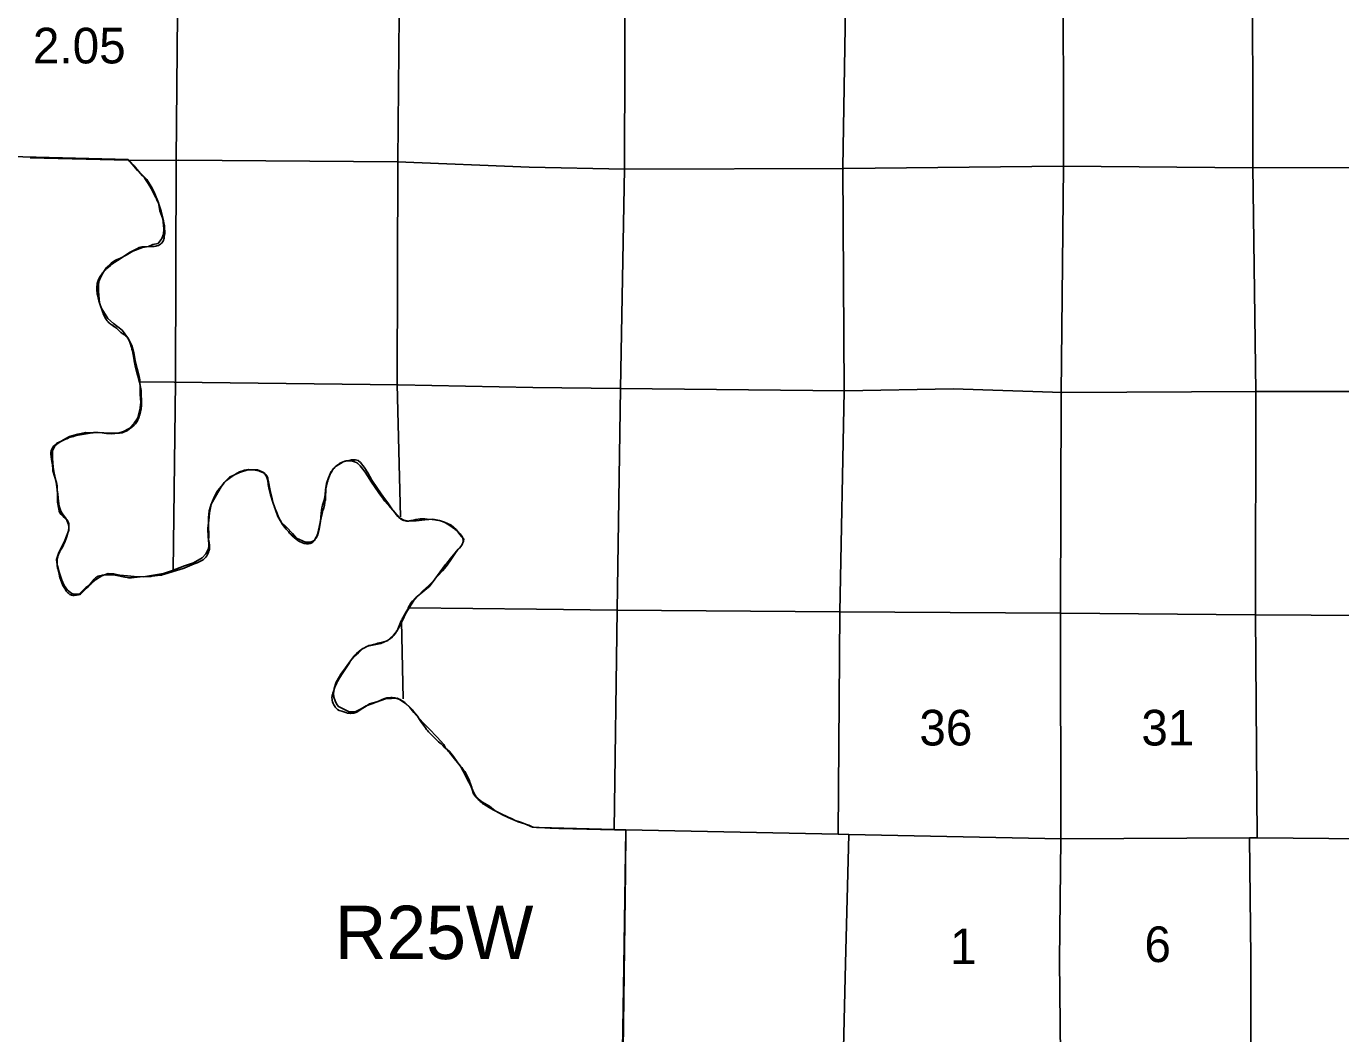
# Model space of a CAD drawing. Extents: x 77230 to 630905, y 790554 to 1662844.
# Drawn here: x 393234 to 424390, y 1547927 to 1571817 of the extents above; entities that cross this region are included whole.
import ezdxf

# ---------------------------------------------------------------- set-up
doc = ezdxf.new("R2010")
doc.units = 0
for name, color, linetype in [('Level 15', 7, 'Continuous'), ('Level 16', 7, 'Continuous'), ('Level 18', 7, 'Continuous'), ('Level 28', 7, 'Continuous'), ('Level 32', 7, 'Continuous'), ('Level 43', 7, 'Continuous')]:
    doc.layers.add(name, color=color, linetype=linetype)

msp = doc.modelspace()

# ---------------------------------------------------------------- linework, layer by layer
at = {"layer": 'Level 15'}
for points in [[(417840, 1586717), (417864, 1584365), (417830, 1579015), (417810, 1573772), (417815, 1568484), (417765, 1563114), (417749, 1557907), (417758, 1552537), (417724, 1549661)], [(434907, 1552506), (432953, 1552522), (432823, 1552523), (427671, 1552544), (427513, 1552528), (422410, 1552574), (422224, 1552572), (417760, 1552549), (412728, 1552648), (412474, 1552660), (407442, 1552760)], [(417724, 1549661), (417746, 1547411), (417738, 1542145), (417700, 1536906), (417692, 1531584), (417689, 1526263)]]:
    msp.add_lwpolyline(points, dxfattribs=at)
at = {"layer": 'Level 16'}
for points in [[(407446, 1584446), (407536, 1579006), (407433, 1573713), (407417, 1568435), (407322, 1563225), (407238, 1557970), (407168, 1552768)], [(412712, 1584452), (412696, 1578980), (412675, 1573704), (412585, 1568465), (412617, 1563165), (412520, 1557929), (412474, 1552660)], [(422260, 1579068), (422260, 1579059), (422302, 1573763), (422310, 1568489), (422377, 1563158), (422369, 1557864), (422410, 1552574)], [(402143, 1575558), (402087, 1573847), (402040, 1568615), (402028, 1563319), (402103, 1560186)], [(396845, 1574644), (396835, 1573856), (396784, 1568648), (396769, 1563376), (396713, 1558915)], [(405151, 1568475), (402032, 1568602), (396832, 1568645), (395671, 1568636)], [(430925, 1568456), (427612, 1568479), (422304, 1568459), (417811, 1568498), (412609, 1568441), (407419, 1568429), (405151, 1568475)], [(405240, 1563250), (402052, 1563317), (396741, 1563379), (395933, 1563387)], [(431276, 1563155), (427652, 1563159), (422379, 1563158), (417795, 1563132), (415205, 1563219), (412635, 1563175), (407312, 1563229), (405240, 1563250)], [(405330, 1557994), (402311, 1558024)], [(435168, 1557795), (432929, 1557807), (427665, 1557826), (422359, 1557864), (417755, 1557897), (412512, 1557933), (407238, 1557972), (405330, 1557994)], [(402128, 1557709), (402166, 1555869)], [(412728, 1552648), (412648, 1549591)], [(422224, 1552572), (422260, 1549746)], [(422260, 1549746), (422258, 1547455), (422316, 1542130), (422366, 1536889), (422412, 1531588), (422437, 1526179), (422367, 1520911)], [(412648, 1549591), (412604, 1547573), (412546, 1542289), (412502, 1537017), (412488, 1531718), (412435, 1526374)]]:
    msp.add_lwpolyline(points, dxfattribs=at)
at = {"layer": 'Level 18'}
for points in [[(393861, 1561471), (393855, 1561559), (393855, 1561691), (393858, 1561747), (393871, 1561791), (393916, 1561872), (393987, 1561928), (394115, 1562010), (394258, 1562089), (394455, 1562142), (394642, 1562184), (394821, 1562179), (394974, 1562186), (395139, 1562161), (395263, 1562153), (395415, 1562168), (395540, 1562208), (395669, 1562276), (395793, 1562409), (395874, 1562531), (395925, 1562710), (395950, 1562894), (395934, 1563094), (395932, 1563227), (395928, 1563435), (395911, 1563511), (395861, 1563690), (395814, 1563895), (395786, 1564075), (395735, 1564246), (395654, 1564407), (395503, 1564607), (395403, 1564689), (395300, 1564769), (395169, 1564885), (395104, 1564988), (395007, 1565141), (394969, 1565260), (394948, 1565528), (394947, 1565670), (394955, 1565761), (395003, 1565872), (395050, 1565965), (395128, 1566092), (395244, 1566198), (395348, 1566272), (395452, 1566314), (395604, 1566389), (395763, 1566484), (395985, 1566572), (396131, 1566597), (396236, 1566645), (396356, 1566665), (396449, 1566785), (396484, 1566888), (396493, 1567014), (396473, 1567248), (396403, 1567437), (396364, 1567631), (396282, 1567841), (396213, 1567992), (396090, 1568182), (396014, 1568265), (395870, 1568399), (395823, 1568452), (395751, 1568539), (395671, 1568636), (395649, 1568655), (391586, 1568764)], [(401097, 1561517), (401034, 1561536), (400942, 1561539), (400747, 1561485), (400581, 1561384), (400457, 1561257), (400398, 1561110), (400350, 1560975), (400327, 1560831), (400317, 1560706), (400292, 1560576), (400254, 1560461), (400239, 1560394), (400227, 1560274), (400207, 1560075), (400200, 1560025), (400178, 1559884), (400146, 1559760), (400108, 1559679), (400041, 1559614), (399967, 1559582), (399851, 1559582), (399640, 1559678), (399546, 1559789), (399399, 1559936), (399275, 1560056), (399194, 1560193), (399131, 1560376), (399074, 1560531), (399019, 1560705), (398982, 1560868), (398968, 1560948), (398956, 1561048), (398927, 1561144), (398873, 1561227), (398825, 1561254), (398716, 1561298), (398508, 1561306), (398291, 1561238), (398053, 1561122), (397921, 1561001), (397851, 1560892), (397746, 1560706), (397620, 1560485), (397571, 1560328), (397552, 1560167), (397551, 1559981), (397560, 1559733), (397556, 1559617), (397557, 1559563), (397563, 1559479), (397542, 1559410), (397486, 1559307), (397399, 1559209), (397197, 1559096), (396981, 1559022), (396677, 1558900), (396488, 1558842), (396298, 1558805), (396013, 1558760), (395787, 1558768), (395635, 1558783), (395450, 1558798), (395303, 1558835), (395171, 1558839), (395026, 1558784), (394878, 1558687), (394764, 1558587), (394647, 1558505), (394576, 1558439), (394486, 1558354), (394380, 1558354), (394310, 1558364), (394210, 1558449), (394134, 1558559), (394080, 1558683), (394010, 1558872), (393974, 1559021), (393958, 1559105), (393953, 1559171), (394002, 1559338), (394089, 1559514), (394147, 1559619), (394244, 1559869), (394244, 1559907), (394243, 1559957), (394228, 1560021), (394198, 1560105), (394190, 1560121), (394161, 1560164), (394091, 1560253), (394052, 1560322), (394012, 1560440), (393992, 1560626), (393979, 1560732), (393963, 1560822), (393948, 1560960), (393926, 1561077), (393894, 1561217), (393873, 1561353), (393861, 1561471)], [(405384, 1552821), (405236, 1552828), (405051, 1552907), (404950, 1552945), (404821, 1552982), (404654, 1553058), (404524, 1553121), (404351, 1553214), (404211, 1553322), (404100, 1553386), (404029, 1553429), (403943, 1553495), (403893, 1553547), (403837, 1553618), (403793, 1553739), (403755, 1553836), (403691, 1553947), (403656, 1554025), (403589, 1554150), (403534, 1554253), (403445, 1554378), (403361, 1554498), (403265, 1554617), (403171, 1554701), (403132, 1554789), (402973, 1554958), (402775, 1555161), (402650, 1555295), (402552, 1555395), (402418, 1555541), (402322, 1555661), (402220, 1555755), (402092, 1555843), (402025, 1555882), (401889, 1555878), (401748, 1555867), (401525, 1555793), (401428, 1555747), (401292, 1555701), (401170, 1555632), (401027, 1555556), (400887, 1555561), (400633, 1555683), (400604, 1555722), (400571, 1555784), (400554, 1555817), (400526, 1555907), (400513, 1555991), (400531, 1556113), (400582, 1556267), (400689, 1556457), (400800, 1556601), (400921, 1556773), (400999, 1556865), (401106, 1556961), (401206, 1557053), (401321, 1557117), (401476, 1557148), (401638, 1557179), (401798, 1557254), (401934, 1557381), (402015, 1557472), (402086, 1557600), (402160, 1557745), (402223, 1557887), (402306, 1558030), (402423, 1558203), (402527, 1558321), (402635, 1558429), (402775, 1558553), (402871, 1558653), (402987, 1558784), (403103, 1558902), (403183, 1559005), (403285, 1559140), (403388, 1559304), (403450, 1559387), (403499, 1559444), (403554, 1559515), (403600, 1559604), (403605, 1559658), (403513, 1559769), (403429, 1559879), (403303, 1559987), (403146, 1560058), (403027, 1560098), (402871, 1560127), (402677, 1560112), (402475, 1560086), (402299, 1560081), (402185, 1560103), (402084, 1560161), (401916, 1560347), (401807, 1560519), (401703, 1560649), (401555, 1560855), (401427, 1561053), (401328, 1561229), (401246, 1561358), (401158, 1561472), (401097, 1561517)], [(405384, 1552821), (407168, 1552768), (407442, 1552760), (407401, 1549518)], [(407401, 1549518), (407365, 1547542), (407301, 1542250), (407239, 1536976), (407211, 1531759), (409819, 1531746), (409752, 1526450), (412435, 1526374), (417689, 1526263), (417667, 1520973), (417653, 1515469), (417654, 1515315), (422612, 1515279), (427579, 1515225)]]:
    msp.add_lwpolyline(points, dxfattribs=at)
at = {"layer": 'Level 43'}
for points in [[(393328, 1568699), (395647, 1568640), (395656, 1568633), (395671, 1568622), (395694, 1568602), (395723, 1568572), (395746, 1568548), (395788, 1568505), (395820, 1568466), (395894, 1568383), (395989, 1568274)], [(395989, 1568274), (396033, 1568223), (396047, 1568205), (396061, 1568184), (396104, 1568114), (396162, 1568022), (396179, 1567995), (396190, 1567973), (396305, 1567759), (396318, 1567726), (396339, 1567681), (396356, 1567643), (396389, 1567552), (396407, 1567501), (396427, 1567434), (396483, 1567214), (396495, 1567143), (396508, 1567082), (396511, 1567044), (396516, 1566926), (396515, 1566904)], [(396515, 1566904), (396503, 1566831), (396499, 1566796), (396493, 1566767), (396484, 1566740), (396471, 1566715), (396458, 1566691), (396444, 1566676), (396430, 1566662), (396415, 1566652), (396392, 1566637), (396364, 1566622), (396332, 1566607), (396303, 1566601), (396265, 1566594), (396242, 1566593), (396226, 1566592), (395993, 1566587), (395969, 1566584), (395941, 1566576), (395912, 1566567), (395868, 1566549), (395684, 1566450), (395457, 1566303), (395334, 1566220), (395310, 1566204), (395279, 1566183), (395257, 1566166)], [(395257, 1566166), (395229, 1566145), (395142, 1566071), (395117, 1566049), (395090, 1566022), (395065, 1565993), (395044, 1565968), (395021, 1565938), (395000, 1565908), (394988, 1565892), (394975, 1565871), (394961, 1565844), (394947, 1565813), (394937, 1565789), (394927, 1565763), (394921, 1565742), (394917, 1565727), (394912, 1565688), (394908, 1565647), (394906, 1565607), (394907, 1565569), (394909, 1565535), (394911, 1565503), (394914, 1565483), (394916, 1565471), (394920, 1565450), (394955, 1565307), (395046, 1565028), (395059, 1564995), (395072, 1564965), (395092, 1564921), (395116, 1564882), (395128, 1564865), (395154, 1564830), (395171, 1564809), (395191, 1564788), (395208, 1564773), (395222, 1564762), (395245, 1564744), (395261, 1564735), (395312, 1564701), (395339, 1564684), (395351, 1564675), (395374, 1564656)], [(395374, 1564656), (395398, 1564634), (395429, 1564605), (395453, 1564581), (395475, 1564559), (395487, 1564550), (395508, 1564535), (395561, 1564502), (395576, 1564491), (395578, 1564489), (395591, 1564477), (395605, 1564463), (395620, 1564448), (395627, 1564439), (395637, 1564426), (395667, 1564373), (395678, 1564346), (395703, 1564276), (395715, 1564243), (395727, 1564206), (395738, 1564163), (395748, 1564123), (395759, 1564077), (395767, 1564036), (395785, 1563943), (395794, 1563887), (395802, 1563846), (395826, 1563724), (395866, 1563571), (395870, 1563555), (395879, 1563526), (395914, 1563380), (395948, 1563222), (395951, 1563203), (395954, 1563180), (395957, 1563159), (395957, 1563137), (395968, 1562888), (395967, 1562859), (395964, 1562827), (395956, 1562747), (395942, 1562671), (395921, 1562588), (395912, 1562557), (395904, 1562538), (395895, 1562519), (395879, 1562486), (395867, 1562463), (395853, 1562438), (395837, 1562414), (395820, 1562390), (395789, 1562360), (395734, 1562309), (395707, 1562286), (395680, 1562267), (395635, 1562234), (395600, 1562215), (395565, 1562199)], [(395565, 1562199), (395537, 1562188), (395504, 1562179), (395477, 1562173), (395442, 1562169), (395382, 1562168), (395213, 1562168), (394939, 1562182), (394907, 1562184), (394874, 1562184), (394838, 1562181), (394814, 1562179), (394794, 1562175), (394465, 1562117), (394422, 1562109), (394396, 1562102), (394355, 1562091), (394254, 1562063), (394224, 1562051), (394191, 1562037), (394161, 1562024), (394129, 1562009), (394001, 1561950), (393974, 1561936), (393953, 1561923), (393930, 1561903), (393907, 1561883), (393888, 1561865), (393873, 1561846), (393857, 1561824), (393847, 1561808), (393836, 1561787), (393829, 1561769), (393823, 1561750), (393816, 1561721), (393815, 1561699), (393817, 1561669), (393823, 1561603), (393832, 1561541), (393842, 1561495), (393849, 1561459), (393852, 1561435), (393854, 1561414), (393860, 1561314), (393863, 1561290), (393866, 1561272), (393901, 1561152), (393946, 1561019), (393950, 1561004), (393952, 1560995), (393958, 1560959), (393964, 1560927), (393969, 1560847), (393973, 1560709), (393974, 1560634), (393973, 1560585), (393973, 1560562), (393974, 1560545), (393976, 1560530), (393979, 1560495), (393987, 1560447), (394012, 1560325), (394015, 1560312), (394022, 1560291), (394030, 1560277), (394060, 1560241), (394108, 1560190), (394166, 1560147), (394181, 1560135), (394193, 1560123), (394204, 1560110), (394213, 1560097), (394221, 1560083), (394230, 1560065), (394235, 1560044), (394241, 1560022), (394243, 1560002), (394244, 1559980), (394244, 1559954), (394241, 1559895), (394238, 1559880)], [(397690, 1560654), (397702, 1560679), (397716, 1560705), (397729, 1560731), (397739, 1560750), (397754, 1560774), (397777, 1560807), (397850, 1560900), (397873, 1560931), (397892, 1560954), (397924, 1560989), (397955, 1561019), (397982, 1561042), (398067, 1561111), (398085, 1561124), (398102, 1561136), (398129, 1561154), (398172, 1561180), (398219, 1561212), (398248, 1561229), (398271, 1561242), (398288, 1561250), (398312, 1561259), (398341, 1561269), (398368, 1561278), (398386, 1561284), (398405, 1561288), (398437, 1561293), (398459, 1561296), (398497, 1561299), (398524, 1561299)], [(398524, 1561299), (398572, 1561298), (398662, 1561292), (398687, 1561288), (398703, 1561285), (398724, 1561280), (398742, 1561275), (398760, 1561268), (398780, 1561260), (398814, 1561245), (398854, 1561224), (398874, 1561213), (398894, 1561199), (398906, 1561191), (398917, 1561180), (398928, 1561168), (398938, 1561154), (398946, 1561141), (398952, 1561125), (398956, 1561110), (398963, 1561089), (398970, 1561056), (399018, 1560808), (399062, 1560607), (399079, 1560532), (399094, 1560485), (399109, 1560442), (399128, 1560391), (399155, 1560325), (399203, 1560202), (399249, 1560108), (399308, 1560005), (399328, 1559974), (399394, 1559895), (399446, 1559834), (399475, 1559800), (399502, 1559772), (399539, 1559737), (399584, 1559697), (399671, 1559624), (399694, 1559607), (399711, 1559597), (399819, 1559555), (399841, 1559551), (399860, 1559548), (399884, 1559546), (399900, 1559545), (399919, 1559547), (399940, 1559549), (399962, 1559555), (399988, 1559563), (400005, 1559571), (400027, 1559586)], [(400027, 1559586), (400041, 1559598), (400053, 1559610), (400064, 1559626), (400075, 1559645), (400106, 1559703), (400119, 1559727), (400137, 1559776), (400148, 1559806), (400163, 1559868), (400200, 1560053), (400211, 1560105), (400223, 1560159), (400244, 1560256), (400254, 1560300), (400263, 1560336), (400276, 1560375), (400299, 1560462), (400314, 1560532), (400318, 1560560), (400323, 1560586), (400325, 1560603), (400327, 1560639), (400328, 1560671), (400331, 1560807), (400332, 1560824), (400335, 1560848), (400350, 1560920), (400372, 1561015), (400378, 1561038), (400388, 1561069), (400405, 1561116), (400421, 1561156), (400437, 1561193), (400444, 1561208), (400460, 1561239), (400473, 1561262), (400485, 1561283), (400511, 1561319), (400529, 1561341), (400548, 1561361), (400573, 1561384), (400586, 1561396), (400616, 1561419), (400642, 1561436), (400669, 1561453), (400704, 1561472), (400743, 1561488), (400783, 1561503), (400800, 1561508), (400814, 1561510), (400837, 1561513), (400863, 1561515), (400901, 1561515), (400933, 1561513), (400954, 1561509), (400966, 1561506), (400993, 1561498), (401008, 1561493), (401033, 1561484), (401058, 1561471), (401071, 1561461), (401091, 1561446), (401108, 1561432), (401133, 1561409), (401147, 1561395), (401179, 1561357), (401267, 1561242), (401420, 1561005), (401578, 1560779), (401608, 1560731), (401653, 1560669)], [(397545, 1559325), (397551, 1559340), (397561, 1559369), (397575, 1559414), (397578, 1559437), (397579, 1559460), (397578, 1559491), (397576, 1559515), (397567, 1559576), (397552, 1559658), (397547, 1559688), (397544, 1559719), (397542, 1559746), (397540, 1559859), (397540, 1559885), (397541, 1559916), (397558, 1560096), (397576, 1560279), (397579, 1560297), (397584, 1560322), (397618, 1560478), (397623, 1560499), (397628, 1560515), (397690, 1560654)], [(401653, 1560669), (401685, 1560623), (401704, 1560593), (401732, 1560558), (401792, 1560488), (401827, 1560450), (401925, 1560339), (401944, 1560316), (402005, 1560239), (402044, 1560191), (402066, 1560170), (402086, 1560152), (402100, 1560140), (402118, 1560126), (402140, 1560115), (402163, 1560105), (402184, 1560099), (402204, 1560094), (402213, 1560091), (402231, 1560087), (402253, 1560084), (402269, 1560083), (402295, 1560085), (402317, 1560087), (402338, 1560090), (402360, 1560095), (402444, 1560114), (402464, 1560118), (402526, 1560130), (402568, 1560136), (402588, 1560138), (402604, 1560137), (402633, 1560137), (402681, 1560133), (402734, 1560130), (402851, 1560122), (402885, 1560119), (402914, 1560114), (402941, 1560111), (402966, 1560106), (403010, 1560096), (403072, 1560081), (403101, 1560071), (403118, 1560065), (403138, 1560058), (403156, 1560050), (403209, 1560015), (403295, 1559959), (403357, 1559918), (403389, 1559896), (403411, 1559879), (403427, 1559865), (403442, 1559852), (403459, 1559838), (403473, 1559824), (403484, 1559814), (403519, 1559777), (403540, 1559748), (403554, 1559728), (403571, 1559699), (403583, 1559669), (403589, 1559650), (403591, 1559636), (403590, 1559605), (403588, 1559582), (403584, 1559564), (403576, 1559548), (403562, 1559526), (403546, 1559504), (403474, 1559417), (403400, 1559332), (403321, 1559234), (403258, 1559156), (403232, 1559125), (403197, 1559080), (403173, 1559050), (402984, 1558796), (402855, 1558618), (402797, 1558544), (402780, 1558526), (402766, 1558513), (402496, 1558294), (402489, 1558288), (402479, 1558279), (402454, 1558255), (402385, 1558188), (402372, 1558175), (402361, 1558162), (402347, 1558145), (402338, 1558131), (402323, 1558100), (402317, 1558083), (402287, 1558023), (402275, 1557998), (402237, 1557932), (402168, 1557807), (402158, 1557788), (402146, 1557765), (402133, 1557737), (402129, 1557730), (402122, 1557714)], [(394238, 1559880), (394231, 1559840), (394222, 1559802), (394197, 1559717), (394148, 1559584), (394118, 1559521), (394097, 1559483), (394075, 1559444), (394059, 1559419), (394044, 1559395), (394029, 1559361), (394013, 1559324), (394001, 1559294), (393989, 1559264), (393980, 1559236), (393973, 1559208), (393966, 1559172), (393964, 1559149), (393962, 1559111), (393965, 1559068), (393967, 1559024), (393970, 1559000), (393976, 1558974), (393981, 1558949), (394012, 1558827), (394031, 1558741), (394043, 1558702), (394104, 1558553), (394145, 1558482), (394169, 1558441), (394181, 1558423), (394197, 1558404), (394217, 1558385), (394241, 1558365), (394252, 1558355), (394269, 1558344), (394287, 1558336), (394305, 1558329), (394323, 1558325), (394347, 1558322), (394366, 1558322), (394399, 1558325), (394427, 1558328), (394465, 1558335), (394487, 1558341), (394506, 1558345), (394522, 1558354), (394545, 1558374), (394609, 1558435), (394690, 1558519), (394742, 1558579), (394846, 1558707), (394858, 1558721), (394872, 1558735), (394892, 1558749), (394907, 1558759), (394924, 1558768), (394941, 1558776), (394973, 1558785), (395013, 1558796), (395043, 1558803), (395076, 1558808), (395107, 1558809), (395141, 1558811), (395183, 1558812), (395220, 1558812), (395255, 1558812), (395279, 1558809), (395304, 1558805), (395339, 1558800), (395566, 1558752)], [(396458, 1558809), (396478, 1558815), (396566, 1558841), (396716, 1558891), (396956, 1558960), (396975, 1558966), (396993, 1558973), (397161, 1559049), (397238, 1559075), (397288, 1559096), (397382, 1559141), (397396, 1559149), (397409, 1559156), (397424, 1559166), (397458, 1559197), (397474, 1559213), (397490, 1559231), (397511, 1559263), (397545, 1559325)], [(395566, 1558752), (395622, 1558743), (395653, 1558739), (395679, 1558736), (395701, 1558736), (395727, 1558737), (395856, 1558756), (395879, 1558758)], [(395879, 1558758), (395911, 1558761), (395935, 1558763), (396130, 1558768), (396162, 1558769), (396186, 1558771), (396211, 1558775), (396419, 1558800), (396440, 1558804), (396458, 1558809)], [(402122, 1557714), (402106, 1557682), (402044, 1557524), (402036, 1557506), (402027, 1557489), (402020, 1557480), (401983, 1557422), (401967, 1557399), (401954, 1557383), (401945, 1557372), (401915, 1557340), (401866, 1557296), (401846, 1557280), (401822, 1557264), (401803, 1557252), (401786, 1557245), (401768, 1557238)], [(401768, 1557238), (401742, 1557229), (401656, 1557207), (401608, 1557195), (401565, 1557185), (401528, 1557175), (401463, 1557160), (401403, 1557144), (401354, 1557129), (401333, 1557121), (401304, 1557108), (401265, 1557089), (401234, 1557071), (401214, 1557059), (401127, 1556995), (401107, 1556980), (401064, 1556941), (401025, 1556903), (400996, 1556870), (400970, 1556835), (400945, 1556802), (400922, 1556770), (400885, 1556709), (400877, 1556698), (400752, 1556506), (400703, 1556435), (400644, 1556338), (400609, 1556280), (400594, 1556250), (400575, 1556211), (400554, 1556165), (400545, 1556143), (400513, 1556044), (400503, 1556003), (400493, 1555974), (400487, 1555949), (400482, 1555924), (400480, 1555908), (400480, 1555890), (400481, 1555861), (400486, 1555833), (400493, 1555796), (400505, 1555760), (400522, 1555723), (400536, 1555700), (400552, 1555676), (400567, 1555659), (400589, 1555638), (400613, 1555617), (400653, 1555595), (400711, 1555572), (400758, 1555556), (400805, 1555541), (400844, 1555531), (400876, 1555527), (400893, 1555525), (400917, 1555524), (400954, 1555525), (400980, 1555528), (400999, 1555532), (401019, 1555537), (401042, 1555545), (401071, 1555555), (401092, 1555568), (401124, 1555588), (401208, 1555648), (401248, 1555674), (401310, 1555710), (401343, 1555731), (401372, 1555747), (401399, 1555758)], [(401399, 1555758), (401426, 1555768), (401545, 1555799), (401625, 1555832), (401671, 1555850), (401711, 1555866), (401731, 1555875), (401758, 1555883), (401778, 1555888), (401790, 1555889), (401813, 1555893), (401847, 1555895), (401878, 1555896), (401909, 1555896), (401936, 1555895), (401966, 1555891), (401995, 1555884), (402042, 1555869), (402075, 1555858), (402095, 1555849), (402117, 1555838), (402144, 1555823), (402163, 1555810), (402186, 1555794), (402208, 1555779), (402242, 1555752), (402308, 1555689), (402393, 1555598), (402415, 1555571), (402505, 1555454), (402554, 1555378), (402599, 1555310), (402694, 1555177), (402719, 1555144), (402743, 1555115), (402768, 1555086), (402804, 1555046), (402901, 1554948), (402926, 1554924), (402956, 1554897), (403007, 1554850), (403064, 1554799), (403133, 1554733), (403175, 1554694), (403216, 1554650), (403242, 1554620), (403264, 1554594), (403380, 1554449), (403527, 1554272), (403557, 1554236), (403583, 1554200), (403606, 1554171), (403625, 1554144), (403665, 1554074), (403692, 1554026), (403708, 1553996), (403729, 1553945), (403749, 1553894), (403766, 1553851), (403773, 1553830), (403791, 1553765), (403801, 1553731), (403816, 1553693), (403827, 1553669), (403839, 1553648), (403872, 1553585), (403901, 1553541), (403933, 1553497), (403961, 1553465), (403989, 1553434), (404012, 1553415), (404047, 1553390), (404080, 1553367), (404206, 1553291), (404245, 1553269), (404300, 1553238), (404396, 1553189), (404459, 1553158), (404671, 1553056), (404734, 1553027), (404808, 1552990), (404896, 1552954), (404993, 1552923), (405049, 1552905), (405090, 1552891), (405149, 1552869), (405223, 1552834), (405251, 1552823)], [(405251, 1552823), (405328, 1552817), (405392, 1552815), (405648, 1552805), (405709, 1552801), (405749, 1552798), (405859, 1552794), (407176, 1552763), (407448, 1552752)], [(407448, 1552752), (407440, 1551754), (407381, 1547544), (407381, 1547535), (407317, 1542255), (407298, 1541051)]]:
    msp.add_lwpolyline(points, dxfattribs=at)

# ---------------------------------------------------------------- texts
at = {"layer": 'Level 16'}
for s, height, p in [('36', 844.8, (414402, 1554762)), ('31', 844.8, (419664, 1554762)), ('1', 845, (415129, 1549577)), ('6', 845, (419737, 1549626))]:
    msp.add_text(s, height=height, dxfattribs=at).set_placement(p)
at = {"layer": 'Level 28'}
msp.add_text('R25W', height=1267.2, dxfattribs=at).set_placement((400546, 1549696))
at = {"layer": 'Level 32'}
msp.add_text('2.05', height=844.8, dxfattribs=at).set_placement((393391, 1570936))

doc.saveas('drawing.dxf')
